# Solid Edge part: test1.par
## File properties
Accuracy: 0.99
Author: CADCIM
Template: Normal.par
Last saved by: CADCIM
Revision: 5
Application: Solid Edge
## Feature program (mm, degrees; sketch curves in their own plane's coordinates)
sketch for "unnamed Protrusion 1" #1 plane through (0, 0, 0) normal (0, 0, 1) x-axis (1, 0, 0)
  line (-47.52, 0) -> (-47.52, 46.944)
  line (-47.52, 46.944) -> (47.52, 46.944)
  line (47.52, 46.944) -> (47.52, 0)
  line (47.52, 0) -> (-47.52, 0)
sketch for "unnamed Protrusion 1" #2 plane through (0, 0, 0) normal (0, 0, 1) x-axis (1, 0, 0)
  circle centre (-33.4173, 33.1293) radius 7.1111
sketch for "unnamed Protrusion 1" #3 plane through (0, 0, 0) normal (0, 0, 1) x-axis (1, 0, 0)
  circle centre (0, 13.2015) radius 7.2161
sketch for "unnamed Protrusion 1" #4 plane through (0, 0, 0) normal (0, 0, 1) x-axis (1, 0, 0)
  circle centre (36.4831, 33.1293) radius 6.1622
extrude "unnamed Protrusion 1" add finite 6.35 along +normal
sketch for "ExtrudedProtrusion_2" #1 plane through (0, 23.472, 6.35) normal (0, 0, 1) x-axis (0, 1, 0)
sketch for "ExtrudedProtrusion_2" #2 plane through (0, 23.472, 6.35) normal (0, 0, 1) x-axis (0, 1, 0)
sketch for "ExtrudedProtrusion_2" #3 plane through (0, 23.472, 6.35) normal (0, 0, 1) x-axis (0, 1, 0)
  circle centre (-10.2705, 0) radius 7.2161
extrude "ExtrudedProtrusion_2" add finite 28.575 along -normal
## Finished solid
Body 1: solid body, 12 faces, 18 edges, 8 vertices.
  Faces by surface: plane 9, cylinder 3
  Edges by curve: line 12, circle 6
Bounding box of the edges (mm): 95.040 x 46.944 x 28.575, from (-47.52, 0, -22.225) to (47.52, 46.944, 6.35).
Cylindrical faces by radius (mm): R6.1622 x1, R7.1111 x1, R7.2161 x1
Planar faces by outward normal: +x 1, +y 1, +z 1, -x 1, -y 1, -z 4
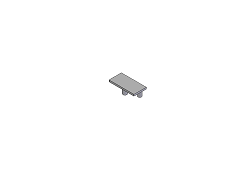
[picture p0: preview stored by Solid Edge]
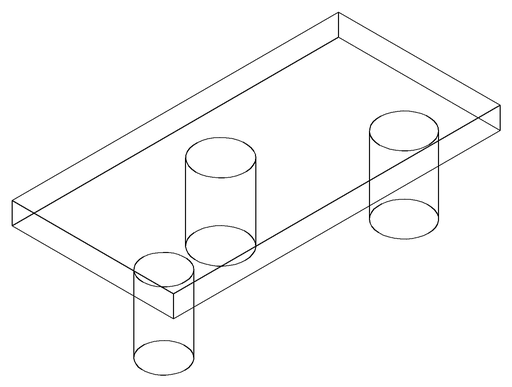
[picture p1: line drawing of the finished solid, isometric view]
